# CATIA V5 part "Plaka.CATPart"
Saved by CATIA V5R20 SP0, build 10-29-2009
Part number: Part1
Bounding box of the stored display mesh (mm): x -10 to 114, y -50 to 50, z -10 to 10
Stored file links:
  C:\Users\metin\Desktop\CatiaDers\Plaka.CATPart
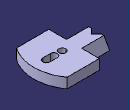
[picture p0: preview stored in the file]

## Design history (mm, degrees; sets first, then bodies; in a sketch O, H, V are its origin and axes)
Body1 (main body)
  Sketch1 on xy-plane, origin (0, 0, 0), H (1, 0, 0), V (0, 1, 0)
    point P1 (0, 0)
    line L1 (0, 0) -> (-10, 10)
    point P2 (-10, 10)
    line L2 (-10, 10) -> (-10, 15)
    point P3 (-10, 15)
    line L3 (-10, 15) -> (34, 15)
    point P4 (34, 15)
    line L4 (34, 15) -> (34, 50)
    point P5 (34, 50)
    point P6 (34, 50)
    line L5 (34, 50) -> (97.7386, 50)
    point P7 (97.7386, 50)
    point P8 (97.7386, -50)
    point P9 (34, -50)
    line L6 (34, -50) -> (97.7386, -50)
    point P10 (-10, -10)
    point P11 (0, 0)
    line L7 (0, 0) -> (-10, -10)
    point P12 (-10, -15)
    line L8 (-10, -10) -> (-10, -15)
    point P13 (34, -15)
    line L9 (-10, -15) -> (34, -15)
    point P14 (34, -50)
    line L10 (34, -15) -> (34, -50)
    arc A1 centre (29, 0) radius 85 from (97.7386, 50) to (97.7386, -50) cw
    point P15 (29, 0)
    construction line L11 (74, 0) -> (89, 0)
    point P16 (74, 0)
    line L12 (74, 7) -> (89, 7)
    line L13 (89, -7) -> (74, -7)
    arc A2 centre (89, 0) radius 7 from (89, 7) to (89, -7) cw
    arc A3 centre (74, 0) radius 7 from (74, -7) to (74, 7) cw
    angle L1 H = 135
    distance P1 O = 0
    length L1 H = 10
    distance L2 A1 = 124
    distance L10 A1 = 80
    distance L5 L6 = 100
    distance L3 L9 = 30
    radius A1 = 85
    distance L11 L12 = 7
    length L11 = 15
    distance P16 P15 = 45
    coincidence: P1 H, P6 L4, P5 P6, P16 H, P1 P11, P9 P14
    vertical: L2 V, L4 V
    horizontal: L3 H, L5 H, L11 H
    symmetry: P7 P8 H, P6 P9 H, L5 L6 H, P2 P10 H, P1 P11 H, L1 L7 H, P3 P12 H, L2 L8 H, P4 P13 H, L3 L9 H, P5 P14 H, L4 L10 H
    tangency: A2 L12, A3 L12, A2 L13, A3 L13
  Pad1: profile Sketch1, direction (0, 0, 1), length 10, mirrored extent
  Sketch2 on face of Pad1 from Sketch1.L8, origin (-10, 0, 0), H (0, -1, 0), V (0, 0, 1)
    point P1 (15, -10)
    point P2 (15, 10)
    line L1 (15, -10) -> (15, 10)
    line L2 (15, 10) -> (26.547, -10)
    point P3 (26.547, -10)
    line L3 (26.547, -10) -> (15, -10)
    point P4 (-15, 10)
    point P5 (-15, -10)
    line L4 (-15, -10) -> (-15, 10)
    point P6 (-26.547, -10)
    line L5 (-15, 10) -> (-26.547, -10)
    line L6 (-26.547, -10) -> (-15, -10)
    reference projected line E1 (15, -10) -> (50, -10) from edge [start face of Pad1 | face of Pad1 from Sketch1.L10]
    reference projected line E2 (-15, -10) -> (-15, 10) from edge [face of Pad1 from Sketch1.L2 | face of Pad1 from Sketch1.L3]
    reference projected line E3 (-15, 10) -> (-10, 10) from edge [face of Pad1 from Sketch1.L2 | end face of Pad1]
    angle L2 L5 = 60
    horizontal: L3 H
    symmetry: P2 P4 V, P1 P5 V, L1 L4 V, P3 P6 V, L2 L5 V, L3 L6 V
    coincidence: L3 E1, L4 E2, P4 E3
  Pad2: profile Sketch2, direction (-1, 0, 0), up to face of Pad1 from Sketch1.L10
  Sketch3 on end face of Pad1, origin (0, 0, 10), H (1, 0, 0), V (0, 1, 0)
    circle A1 centre (57.377, 0) radius 7
    point P1 (57.377, 0)
    reference projected arc E1 centre (89, 0) radius 7 from (89, -7) to (89, 7) ccw from edge [end face of Pad1 | face of Pad1 from Sketch1.A2]
    distance P1 E1 = 38.623
    radius A1 = 7
    coincidence: P1 H
  Pocket1: profile Sketch3, direction (0, 0, -1), through (limit type 3)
